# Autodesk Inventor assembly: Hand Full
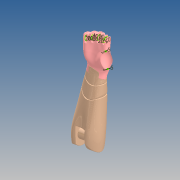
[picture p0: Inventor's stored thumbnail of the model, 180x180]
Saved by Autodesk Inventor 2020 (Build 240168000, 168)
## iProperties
Created: 2019-10
Part Number: Hand Full
Document SubType Name: Assembly
Designer: yello
Author: yello
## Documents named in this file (11)
- C:\Users\yello\Documents\Mechanical Hand\Prototype 2 (Realistic Hand)\Hand Full.iam
- C:\Users\yello\Documents\Mechanical Hand\Prototype 2 (Realistic Hand)\Palm.ipt
- C:\Users\yello\Documents\Mechanical Hand\Prototype 2 (Realistic Hand)\Wrist Rotation.ipt
- C:\Users\yello\Documents\Mechanical Hand\Prototype 2 (Realistic Hand)\Arm to Wrist Connection.ipt
- C:\Users\yello\Documents\Mechanical Hand\Prototype 2 (Realistic Hand)\Arm.ipt
- C:\Users\yello\Documents\Mechanical Hand\Prototype 2 (Realistic Hand)\Segment Thumb Finger Bottom.ipt
- C:\Users\yello\Documents\Mechanical Hand\Prototype 2 (Realistic Hand)\Segment Thumb Finger Middle.ipt
- C:\Users\yello\Documents\Mechanical Hand\Prototype 2 (Realistic Hand)\Segment Thumb Finger Top.ipt
- C:\Users\yello\Documents\Mechanical Hand\Prototype 2 (Realistic Hand)\Segment Index Finger Bottom.ipt
- C:\Users\yello\Documents\Mechanical Hand\Prototype 2 (Realistic Hand)\Segment Index Finger Middle.ipt
- C:\Users\yello\Documents\Mechanical Hand\Prototype 2 (Realistic Hand)\Segment Index Finger Top.ipt
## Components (10 placed, 10 different names)
1. Palm:1 — Rotational:1, Rotational:2, Rotational:5
2. Wrist Rotation:1 — Rotational:1, Mate:1, Mate:2, Mate:4
3. Arm to Wrist Connection:1 — Mate:1, Mate:2, Mate:3
4. Arm:1 — Mate:3, Mate:4
5. Segment Thumb Finger Bottom:1 — Rotational:2, Rotational:3
6. Segment Thumb Finger Middle:1 — Rotational:3, Rotational:4
7. Segment Thumb Finger Top:1 — Rotational:4
8. Segment Index Finger Bottom:1 — Rotational:5, Rotational:6
9. Segment Index Finger Middle:1 — Rotational:6, Rotational:7
10. Segment Index Finger Top:1 — Rotational:7
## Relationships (11: RevoluteJoint 7, Mate 4)
- Rotational:1 [RevoluteJoint]: Palm:1 ↔ Wrist Rotation:1
- Mate:1: Wrist Rotation:1 ↔ Arm to Wrist Connection:1
- Mate:2: Wrist Rotation:1 ↔ Arm to Wrist Connection:1
- Mate:3: Arm to Wrist Connection:1 ↔ Arm:1
- Mate:4: Wrist Rotation:1 ↔ Arm:1
- Rotational:2 [RevoluteJoint]: Palm:1 ↔ Segment Thumb Finger Bottom:1
- Rotational:3 [RevoluteJoint]: Segment Thumb Finger Bottom:1 ↔ Segment Thumb Finger Middle:1
- Rotational:4 [RevoluteJoint]: Segment Thumb Finger Middle:1 ↔ Segment Thumb Finger Top:1
- Rotational:5 [RevoluteJoint]: Palm:1 ↔ Segment Index Finger Bottom:1
- Rotational:6 [RevoluteJoint]: Segment Index Finger Bottom:1 ↔ Segment Index Finger Middle:1
- Rotational:7 [RevoluteJoint]: Segment Index Finger Middle:1 ↔ Segment Index Finger Top:1
